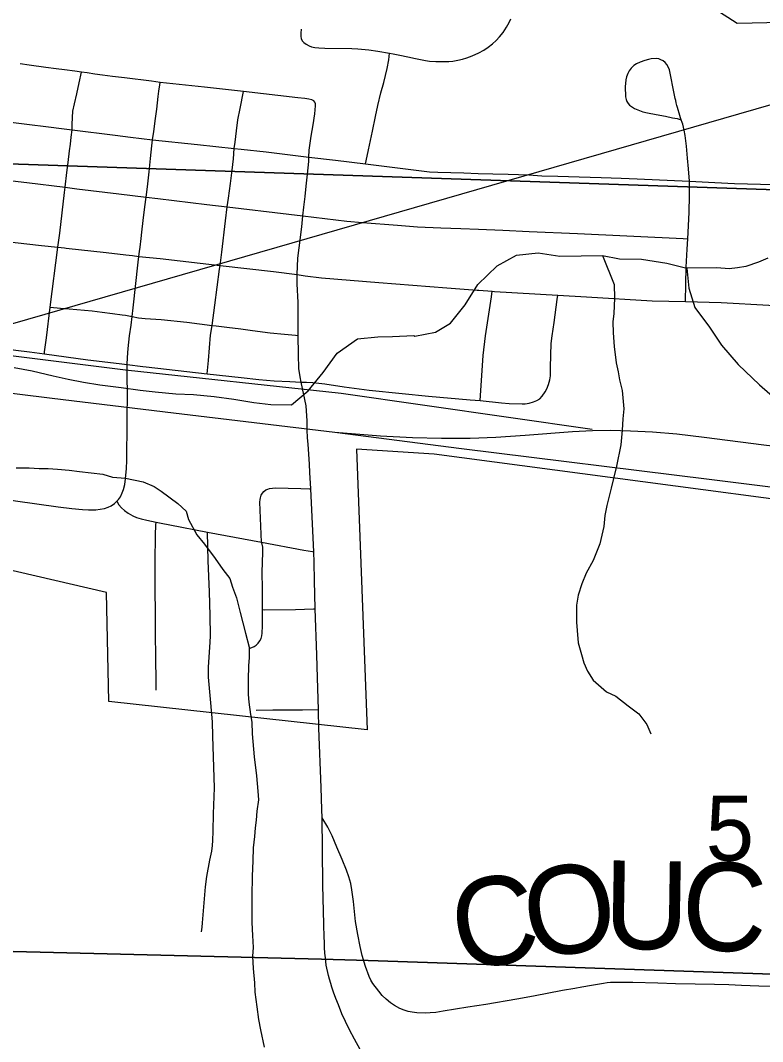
# Model space of a CAD drawing. Extents: x 0 to 34, y 0 to 22.
# Drawn here: x 14.532 to 15.01, y 17.412 to 18.07 of the extents above; entities that cross this region are included whole.
import ezdxf

# ---------------------------------------------------------------- set-up
doc = ezdxf.new("R2010")
doc.units = 0
for name, color, linetype in [('GM_X_City_Street', 7, 'Continuous'), ('GM_X_Corporation', 7, 'Continuous'), ('GM_X_County_Road', 7, 'Continuous'), ('GM_X_Major_River', 7, 'Continuous'), ('GM_X_Minor_River', 7, 'Continuous'), ('GM_X_Rail_Line', 7, 'Continuous'), ('GM_X_Section_Text', 7, 'Continuous'), ('GM_X_State_Route', 7, 'Continuous'), ('GM_X_Township_Road', 7, 'Continuous'), ('GM_X_Township_Road_Text', 7, 'Continuous'), ('SH_Text', 7, 'Continuous')]:
    doc.layers.add(name, color=color, linetype=linetype)

msp = doc.modelspace()

# ---------------------------------------------------------------- linework, layer by layer
at = {"layer": 'GM_X_City_Street'}
for points in [[(14.76987, 18.04884), (14.77212, 18.04844), (14.7765, 18.04767), (14.78166, 18.04664), (14.78647, 18.04554), (14.79308, 18.04416), (14.79561, 18.04378), (14.79962, 18.04349), (14.8081, 18.0436), (14.81055, 18.04383), (14.81391, 18.04436), (14.81687, 18.04502), (14.81962, 18.04585), (14.82308, 18.04715), (14.82737, 18.04911), (14.8305, 18.05081), (14.83345, 18.0527), (14.83621, 18.05484), (14.8385, 18.05698), (14.84067, 18.05935), (14.84299, 18.06226), (14.84527, 18.06561), (14.84695, 18.06868), (14.84809, 18.07102)], [(14.71298, 18.06429), (14.71278, 18.06188), (14.71265, 18.05969), (14.71288, 18.05834), (14.71355, 18.0569), (14.71459, 18.05575), (14.71604, 18.05474), (14.71801, 18.05367), (14.71956, 18.0531), (14.72173, 18.05262), (14.72427, 18.05237), (14.72815, 18.05223), (14.74546, 18.05199), (14.74935, 18.05176), (14.75646, 18.05117), (14.76227, 18.05029), (14.76987, 18.04884)], [(14.75439, 17.97764), (14.75473, 17.97967), (14.75618, 17.98662), (14.75886, 17.99873), (14.76078, 18.00809), (14.76222, 18.01513), (14.76417, 18.02343), (14.76609, 18.02999), (14.76837, 18.03909), (14.76929, 18.04464), (14.76987, 18.04884)], [(14.7179, 17.98196), (14.71815, 17.98637), (14.71926, 17.99549), (14.72064, 18.0028), (14.72181, 18.00988), (14.72221, 18.01499), (14.72211, 18.01628), (14.72166, 18.01742), (14.72096, 18.01815), (14.71973, 18.01876), (14.7179, 18.0192), (14.71531, 18.01968), (14.7107, 18.02014), (14.67577, 18.02432), (14.65062, 18.02693), (14.622, 18.03011), (14.61638, 18.0308), (14.59906, 18.03298), (14.59144, 18.03397), (14.58489, 18.03483), (14.57992, 18.0355), (14.57503, 18.03615), (14.57129, 18.03666), (14.56705, 18.03724), (14.56049, 18.03814), (14.55506, 18.03888), (14.54839, 18.03978), (14.53767, 18.04122), (14.53193, 18.04197)], [(14.963, 17.96648), (14.96256, 17.97437), (14.96189, 17.98122), (14.9612, 17.98892), (14.96037, 17.99599), (14.95973, 17.99934), (14.95874, 18.0031), (14.95834, 18.00436), (14.95777, 18.00609), (14.95736, 18.00731), (14.95691, 18.00873), (14.95643, 18.01027), (14.95581, 18.01234), (14.95534, 18.01398), (14.95501, 18.01518), (14.95455, 18.01697), (14.95421, 18.01835), (14.95389, 18.01972), (14.95315, 18.02297), (14.95252, 18.02617), (14.95112, 18.03382), (14.95022, 18.03826), (14.94945, 18.04017), (14.94851, 18.04166), (14.94748, 18.04286), (14.94615, 18.04398), (14.94469, 18.04473), (14.94331, 18.04525), (14.9417, 18.04541), (14.9385, 18.0453), (14.93659, 18.04493), (14.93424, 18.04421), (14.93126, 18.04311), (14.92889, 18.04198), (14.92731, 18.04102), (14.92548, 18.03928), (14.92425, 18.03745), (14.92337, 18.03579), (14.92259, 18.03358), (14.9221, 18.03165), (14.92178, 18.02949), (14.92171, 18.0274), (14.92189, 18.0209), (14.92223, 18.019), (14.92277, 18.01782), (14.92353, 18.01656), (14.92453, 18.01533), (14.92578, 18.01447), (14.92772, 18.01338), (14.92986, 18.01236), (14.93308, 18.01115), (14.93603, 18.01041), (14.94164, 18.00944), (14.9476, 18.00827), (14.95212, 18.00737), (14.95362, 18.00706), (14.95506, 18.00675), (14.95641, 18.00646), (14.95777, 18.00609)], [(14.54744, 17.85518), (14.54762, 17.85658), (14.54875, 17.86551), (14.55127, 17.88542), (14.55616, 17.92395), (14.55732, 17.93307), (14.56042, 17.95925), (14.5608, 17.96254), (14.56193, 17.97212), (14.5627, 17.9784), (14.56367, 17.98601), (14.56422, 17.99038), (14.56476, 17.99478), (14.56533, 17.99959), (14.56542, 18.00323), (14.56582, 18.01156), (14.56687, 18.01631), (14.56836, 18.02267), (14.5699, 18.02973), (14.57129, 18.03666)], [(14.61712, 17.99317), (14.6179, 17.99849), (14.61901, 18.00692), (14.61985, 18.01283), (14.62034, 18.01688), (14.62086, 18.02106), (14.62127, 18.02437), (14.62179, 18.02845), (14.622, 18.03011)], [(14.65233, 17.84236), (14.6531, 17.85105), (14.65456, 17.86733), (14.65552, 17.87344), (14.65733, 17.88652), (14.66019, 17.90976), (14.66063, 17.91218), (14.66184, 17.92066), (14.66423, 17.94085), (14.66532, 17.94996), (14.66608, 17.95564), (14.66734, 17.96496), (14.66851, 17.97364), (14.66931, 17.9809), (14.66983, 17.98761), (14.67034, 17.99167), (14.67127, 17.99882), (14.6722, 18.00609), (14.67351, 18.01335), (14.67577, 18.02432)], [(14.49509, 18.00812), (14.49845, 18.00791), (14.50719, 18.00686), (14.52592, 18.0045), (14.53785, 18.00305), (14.54846, 18.00175), (14.56024, 18.00028), (14.56533, 17.99959), (14.59308, 17.99608), (14.60298, 17.99483), (14.61712, 17.99317)], [(14.61498, 17.97256), (14.61589, 17.98109), (14.61671, 17.98927), (14.61712, 17.99317)], [(14.61712, 17.99317), (14.64603, 17.99012), (14.66983, 17.98761), (14.67415, 17.98715), (14.69025, 17.98534), (14.7179, 17.98196)], [(14.724, 17.62616), (14.72338, 17.64665), (14.72292, 17.66143), (14.722, 17.69098), (14.7215, 17.70927), (14.72118, 17.72093), (14.72096, 17.72776), (14.71911, 17.76842), (14.71859, 17.77879), (14.7183, 17.78432), (14.71735, 17.79708), (14.71704, 17.80125), (14.71684, 17.80643), (14.71666, 17.81216), (14.7161, 17.82178), (14.71286, 17.8371), (14.71215, 17.84055), (14.71145, 17.84593), (14.71114, 17.85477), (14.71107, 17.86707), (14.71089, 17.88843), (14.7104, 17.90045), (14.71027, 17.90631), (14.7108, 17.91691), (14.71167, 17.92361), (14.71323, 17.93706), (14.71398, 17.9441), (14.71465, 17.94981), (14.71538, 17.95659), (14.71604, 17.96321), (14.71693, 17.97104), (14.71777, 17.97905), (14.7179, 17.98196)], [(14.7179, 17.98196), (14.73502, 17.98008), (14.75439, 17.97764), (14.79564, 17.97259), (14.80102, 17.97218), (14.81761, 17.97178), (14.82694, 17.97152), (14.83644, 17.97126), (14.8462, 17.9709), (14.8596, 17.97052), (14.86798, 17.96998), (14.87834, 17.96966), (14.89212, 17.9692), (14.90612, 17.96881), (14.91912, 17.96842), (14.92947, 17.96802), (14.963, 17.96648)], [(14.51384, 17.96829), (14.53625, 17.96558), (14.5608, 17.96254), (14.56829, 17.96165), (14.59548, 17.95829), (14.61309, 17.95614), (14.62055, 17.95525), (14.65221, 17.9515), (14.66532, 17.94996), (14.70486, 17.9452), (14.71398, 17.9441), (14.74229, 17.94064), (14.75243, 17.93992), (14.77487, 17.93808), (14.78783, 17.93706), (14.80285, 17.93649), (14.81586, 17.9359), (14.82713, 17.93552), (14.84282, 17.93486), (14.85977, 17.934), (14.89086, 17.93268), (14.95911, 17.92952), (14.96205, 17.92932)], [(14.60829, 17.91806), (14.60877, 17.9211), (14.60913, 17.92408), (14.60982, 17.92964), (14.61032, 17.93365), (14.61117, 17.94114), (14.61217, 17.94992), (14.61309, 17.95614), (14.61391, 17.96273), (14.61498, 17.97256)], [(14.96045, 17.8889), (14.96072, 17.90022), (14.96105, 17.91108), (14.96168, 17.92279), (14.96205, 17.92932), (14.96288, 17.94621), (14.96305, 17.95731), (14.963, 17.96648)], [(14.963, 17.96648), (14.97939, 17.96557), (14.99211, 17.96506), (15.05047, 17.96342), (15.07989, 17.96229), (15.08594, 17.9622), (15.10877, 17.96158), (15.14487, 17.9602), (15.15632, 17.95933)], [(14.52497, 17.92744), (14.53623, 17.92618), (14.54566, 17.92513), (14.55616, 17.92395), (14.56046, 17.92347), (14.56146, 17.92336)], [(14.56146, 17.92336), (14.58732, 17.92045), (14.59996, 17.91901), (14.60424, 17.91852), (14.60829, 17.91806)], [(14.82833, 17.82514), (14.82862, 17.83157), (14.83008, 17.85412), (14.8316, 17.86687), (14.83547, 17.89208), (14.83603, 17.89558)], [(14.61097, 17.84714), (14.613, 17.8469), (14.65233, 17.84236), (14.67426, 17.84003), (14.68565, 17.83886), (14.69546, 17.83792), (14.70558, 17.83739), (14.71286, 17.8371), (14.71643, 17.83701), (14.72051, 17.83673), (14.72808, 17.83592), (14.74054, 17.83406), (14.7568, 17.83192), (14.77802, 17.82969), (14.79485, 17.82797), (14.82185, 17.82569), (14.82833, 17.82514), (14.84201, 17.82371), (14.84685, 17.82337), (14.85529, 17.82303), (14.85723, 17.82315), (14.85978, 17.82356), (14.86269, 17.82432), (14.86475, 17.82521), (14.86657, 17.82635), (14.86823, 17.82806), (14.87007, 17.83072), (14.87118, 17.83278), (14.87234, 17.83549), (14.87313, 17.83853), (14.87346, 17.84114), (14.87362, 17.8468), (14.87407, 17.86185), (14.87469, 17.86692), (14.87601, 17.87537), (14.8779, 17.89023), (14.87823, 17.893)], [(14.55127, 17.88542), (14.55785, 17.88477), (14.56334, 17.88424), (14.57327, 17.88347), (14.57815, 17.88289), (14.58479, 17.88205), (14.59129, 17.8813), (14.59752, 17.88049), (14.59981, 17.88013), (14.60189, 17.87969), (14.60399, 17.87928), (14.60803, 17.87851), (14.61236, 17.87813), (14.62262, 17.8774), (14.63921, 17.87566), (14.65552, 17.87344), (14.65813, 17.87325), (14.66501, 17.87253), (14.67404, 17.87135), (14.68145, 17.8703), (14.69301, 17.86882), (14.70221, 17.86786), (14.7092, 17.86723), (14.71107, 17.86707)], [(14.49053, 17.86534), (14.49131, 17.86444), (14.49232, 17.86372), (14.49347, 17.86314), (14.49484, 17.86262), (14.49647, 17.86218), (14.49858, 17.86179), (14.5045, 17.86098), (14.51118, 17.86005), (14.51621, 17.85937), (14.52316, 17.85842), (14.52906, 17.85767), (14.53782, 17.85648), (14.54744, 17.85518), (14.57539, 17.85138), (14.59556, 17.84896), (14.60077, 17.84835), (14.61097, 17.84714)], [(14.67944, 17.66549), (14.68122, 17.66618), (14.6826, 17.66683), (14.68393, 17.66769), (14.68525, 17.66896), (14.68632, 17.67041), (14.68713, 17.67187), (14.68761, 17.67375), (14.68785, 17.67549), (14.68792, 17.6802), (14.68807, 17.69063), (14.68792, 17.70409), (14.68771, 17.71455), (14.68824, 17.72754), (14.68812, 17.73087), (14.68769, 17.73273), (14.68725, 17.73404), (14.68636, 17.75972), (14.68646, 17.76145), (14.68668, 17.76265), (14.68722, 17.76421), (14.68792, 17.7655), (14.68886, 17.76667), (14.69009, 17.7676), (14.6914, 17.76818), (14.69241, 17.76846), (14.69645, 17.76893), (14.71276, 17.7686), (14.71832, 17.76844), (14.71911, 17.76842)], [(14.59413, 17.7604), (14.59552, 17.75813), (14.59709, 17.7562), (14.599, 17.75437), (14.6015, 17.75259), (14.60442, 17.75093), (14.60685, 17.7498), (14.60974, 17.74892), (14.61341, 17.74807), (14.61951, 17.74683), (14.62267, 17.74625), (14.62833, 17.74516), (14.65252, 17.74054), (14.68725, 17.73404), (14.71457, 17.72891), (14.7201, 17.72792), (14.72096, 17.72776)], [(14.61957, 17.63863), (14.61942, 17.64816), (14.61931, 17.65573), (14.61921, 17.66419), (14.61914, 17.6707), (14.61882, 17.72108), (14.61906, 17.7388), (14.61931, 17.74494), (14.61951, 17.74683)], [(14.68807, 17.69063), (14.68946, 17.69052), (14.7093, 17.69067), (14.72074, 17.69098), (14.722, 17.69098)], [(14.68391, 17.62584), (14.69464, 17.62608), (14.70342, 17.62597), (14.71366, 17.62604), (14.724, 17.62616)]]:
    msp.add_lwpolyline(points, dxfattribs=at)
at = {"layer": 'GM_X_Corporation'}
for points in [[(13.27416, 17.49656), (14.09544, 17.48114), (14.72599, 17.4654), (14.75606, 17.4645), (15.84263, 17.42782), (15.88436, 17.42688), (16.48069, 17.41608), (16.48857, 17.73917), (16.51683, 18.87067), (16.5174, 18.89349), (16.54748, 18.89293), (16.75204, 18.88908), (16.75322, 19.06144), (16.75475, 19.28374), (16.76523, 20.32799), (16.7661, 20.4), (11.50006, 20.4)], [(16.44192, 14.8642), (16.44975, 15.46263), (16.45161, 15.59641), (16.46108, 16.1288), (16.46029, 16.26174), (16.46891, 16.92454), (16.47027, 17.00356), (16.4704, 17.01044), (16.48069, 17.41608), (15.88436, 17.42688), (15.84263, 17.42782), (14.75606, 17.4645), (14.72599, 17.4654), (14.09544, 17.48114), (13.27416, 17.49656)]]:
    msp.add_lwpolyline(points, dxfattribs=at)
for points in [[(14.51245, 18.92359), (15.51969, 18.90882), (15.50037, 17.94467), (14.4926, 17.9788)], [(14.12416, 17.75411), (14.12384, 17.99777), (14.12545, 18.21705), (14.2457, 18.21434), (14.49034, 18.19103), (14.78118, 18.15667), (14.88115, 18.1407), (14.99378, 18.06821), (15.18555, 18.07245), (15.22414, 18.0733), (15.17106, 17.87356), (15.20251, 17.8656), (15.18408, 17.73958), (14.79859, 17.79075), (14.74846, 17.79396), (14.75535, 17.61323), (14.58889, 17.63142), (14.58748, 17.70162), (14.28481, 17.77174), (14.28379, 17.80545), (14.2579, 17.80636), (14.24004, 17.80235), (14.21513, 17.79424), (14.20893, 17.79132)], [(14.4926, 17.9788), (15.50037, 17.94467), (15.48158, 16.92817), (14.47088, 16.98467)]]:
    msp.add_lwpolyline(points, close=True, dxfattribs=at)
at = {"layer": 'GM_X_County_Road'}
for points in [[(14.72434, 17.61429), (14.72424, 17.61828), (14.72416, 17.62132), (14.724, 17.62616)], [(14.72786, 17.47663), (14.72775, 17.47945), (14.72747, 17.48801), (14.72681, 17.51299), (14.72662, 17.53602), (14.72634, 17.55647), (14.72616, 17.56191), (14.72583, 17.57596), (14.72434, 17.61429)], [(14.73041, 17.45499), (14.72908, 17.46164), (14.7285, 17.4662), (14.72823, 17.46933), (14.72802, 17.47288), (14.72786, 17.47663)], [(14.75086, 17.40723), (14.7472, 17.41386), (14.74406, 17.41995), (14.74149, 17.4252), (14.73917, 17.43028), (14.73686, 17.43602), (14.73525, 17.44006), (14.73367, 17.44426), (14.73264, 17.44731), (14.73195, 17.4498), (14.73118, 17.45263), (14.73041, 17.45499)]]:
    msp.add_lwpolyline(points, dxfattribs=at)
at = {"layer": 'GM_X_Major_River'}
for points in [[(14.78547, 17.86706), (14.78617, 17.86676), (14.79942, 17.86922), (14.80922, 17.87505), (14.81855, 17.88694), (14.82673, 17.89996), (14.8391, 17.91189), (14.85154, 17.91889), (14.86557, 17.92023), (14.87964, 17.91814), (14.90698, 17.91852), (14.91801, 17.9164), (14.93207, 17.91621), (14.94842, 17.91378)], [(14.94842, 17.91378), (14.96137, 17.91055), (14.96268, 17.89766), (14.96664, 17.88519), (14.97592, 17.87242), (14.98367, 17.86077), (14.99446, 17.84839), (15.00831, 17.8353), (15.01983, 17.82522)], [(14.52809, 17.84646), (14.53949, 17.84437), (14.55319, 17.84119), (14.5627, 17.83907), (14.57259, 17.83696), (14.58323, 17.83524), (14.5969, 17.83357), (14.60906, 17.83187), (14.61893, 17.8309), (14.63222, 17.8296), (14.6436, 17.82903), (14.65689, 17.82774), (14.66942, 17.82605), (14.68235, 17.82399), (14.69336, 17.82265), (14.70663, 17.82249), (14.71747, 17.8314), (14.72712, 17.84332), (14.73601, 17.85561), (14.74912, 17.86493), (14.76237, 17.86629), (14.77184, 17.86645), (14.78547, 17.86706)]]:
    msp.add_lwpolyline(points, dxfattribs=at)
at = {"layer": 'GM_X_Minor_River'}
for points in [[(14.90698, 17.91852), (14.91462, 17.89991), (14.91484, 17.89118), (14.91434, 17.88129), (14.91372, 17.87596), (14.9139, 17.86874), (14.9145, 17.86002), (14.91592, 17.84942), (14.9172, 17.84375), (14.91809, 17.83846), (14.91978, 17.83166), (14.92085, 17.81991), (14.92025, 17.81343), (14.91968, 17.8062), (14.91878, 17.79668), (14.9161, 17.78294), (14.91267, 17.76879), (14.90992, 17.75771), (14.90857, 17.75121), (14.908, 17.74398), (14.90525, 17.7329), (14.90097, 17.72215), (14.89662, 17.71407), (14.89377, 17.70715), (14.8913, 17.69988), (14.89032, 17.69339), (14.89023, 17.68237), (14.89074, 17.67707), (14.89133, 17.6691), (14.89342, 17.66156), (14.89507, 17.65628), (14.89748, 17.65102), (14.90105, 17.64503), (14.90959, 17.63765), (14.91573, 17.63476), (14.92348, 17.6285), (14.93044, 17.62335), (14.93554, 17.61664), (14.93821, 17.61061)], [(15.01359, 17.91683), (15.00758, 17.9144), (14.99931, 17.91153), (14.99402, 17.91064), (14.98872, 17.91013), (14.98074, 17.91069), (14.96137, 17.91055)], [(14.52935, 17.78182), (14.5377, 17.78183), (14.54415, 17.78146), (14.54985, 17.78148), (14.55592, 17.78111), (14.56352, 17.78036), (14.56998, 17.77961), (14.58517, 17.77774), (14.59125, 17.77586), (14.59961, 17.77511), (14.611, 17.77286), (14.61823, 17.76983), (14.62279, 17.7668), (14.63345, 17.75885), (14.63878, 17.75392), (14.64032, 17.74861), (14.64567, 17.73874), (14.65063, 17.73268), (14.6575, 17.72358), (14.66246, 17.71637), (14.66703, 17.71069), (14.66857, 17.70499), (14.67125, 17.69816), (14.67356, 17.68867), (14.67703, 17.67539), (14.67934, 17.66628), (14.67936, 17.65945), (14.679, 17.65451), (14.67865, 17.6454), (14.67868, 17.6359), (14.67908, 17.63097), (14.68025, 17.623), (14.68102, 17.61806), (14.68143, 17.61047), (14.68262, 17.59566), (14.68418, 17.58351), (14.68497, 17.57364), (14.68537, 17.56795), (14.68426, 17.56073), (14.6839, 17.55503), (14.68316, 17.55009), (14.6828, 17.5444), (14.68206, 17.53718), (14.68171, 17.52883), (14.68137, 17.51896), (14.68103, 17.50604), (14.68109, 17.48896), (14.6815, 17.4806), (14.68191, 17.47301), (14.68155, 17.46731), (14.68196, 17.45934), (14.68275, 17.45023), (14.68315, 17.44415), (14.68432, 17.43466), (14.68549, 17.42669), (14.68665, 17.41986), (14.68897, 17.40885)]]:
    msp.add_lwpolyline(points, dxfattribs=at)
at = {"layer": 'GM_X_Rail_Line'}
for points in [[(14.90033, 17.80647), (14.73866, 17.82966), (14.59978, 17.84477), (14.43811, 17.86491), (14.35463, 17.87631), (14.29632, 17.88267), (14.25073, 17.88558), (14.23059, 17.88691), (13.97059, 17.88399), (13.8235, 17.8824), (13.80468, 17.88346), (13.7901, 17.88532), (13.76545, 17.88797)], [(13.74001, 17.86404), (13.79479, 17.85776), (13.8449, 17.85469), (13.92574, 17.85403), (14.08342, 17.85653), (14.25612, 17.85826), (14.28777, 17.85708), (14.31905, 17.85522), (14.36121, 17.85072), (14.46202, 17.838), (14.55254, 17.82673), (14.63073, 17.81732), (14.73449, 17.80474)], [(14.73449, 17.80474), (14.76404, 17.80248), (14.78458, 17.80142), (14.8034, 17.80102), (14.82168, 17.80102), (14.83838, 17.80155), (14.8572, 17.80301), (14.88768, 17.80527), (14.90053, 17.80593), (14.91219, 17.80606), (14.92505, 17.8058), (14.93936, 17.80513), (14.95486, 17.80381), (14.97262, 17.80155), (15.01105, 17.79678), (15.10766, 17.78512), (15.25939, 17.7667), (15.27622, 17.76472), (15.29106, 17.76246), (15.30802, 17.75981), (15.32353, 17.75703)], [(14.73449, 17.80474), (14.81612, 17.79427), (14.97567, 17.77465), (15.12502, 17.75597), (15.14542, 17.75345), (15.16225, 17.7512), (15.18001, 17.74855), (15.19896, 17.74537), (15.21804, 17.74166), (15.23527, 17.73808), (15.25144, 17.7345), (15.26893, 17.73026), (15.29066, 17.72469), (15.31226, 17.71833)]]:
    msp.add_lwpolyline(points, dxfattribs=at)
at = {"layer": 'GM_X_State_Route'}
for points in [[(14.60399, 17.87928), (14.60457, 17.885), (14.60788, 17.91438), (14.60829, 17.91806)], [(14.60829, 17.91806), (14.622, 17.9167), (14.66063, 17.91218)], [(14.66063, 17.91218), (14.69506, 17.90824), (14.71027, 17.90631)], [(14.71027, 17.90631), (14.71549, 17.90549), (14.7261, 17.90422), (14.76304, 17.90124), (14.80669, 17.89785), (14.82632, 17.89632)], [(14.82632, 17.89632), (14.82736, 17.89624), (14.83603, 17.89558)], [(14.83603, 17.89558), (14.83737, 17.89549), (14.87823, 17.893)], [(14.87823, 17.893), (14.89683, 17.89204), (14.93913, 17.8895), (14.96045, 17.8889)], [(14.96045, 17.8889), (14.98342, 17.88842), (15.0143, 17.88665), (15.02884, 17.88565), (15.07549, 17.88285), (15.07745, 17.88277)], [(14.60077, 17.84835), (14.60096, 17.85297), (14.60134, 17.85866), (14.60229, 17.86687), (14.60329, 17.87375), (14.60399, 17.87928)], [(14.60089, 17.82108), (14.6009, 17.82202), (14.60077, 17.84835)], [(14.59413, 17.7604), (14.5952, 17.76157), (14.59645, 17.76329), (14.59764, 17.76566), (14.59842, 17.76787), (14.59921, 17.7711), (14.59978, 17.77482), (14.60032, 17.78147), (14.60065, 17.78657), (14.60083, 17.81159), (14.60089, 17.82108)], [(14.37722, 17.7951), (14.38189, 17.79392), (14.40236, 17.78861), (14.42323, 17.78346), (14.43503, 17.78049), (14.44945, 17.77703), (14.46381, 17.77344), (14.49075, 17.76717), (14.50163, 17.76494), (14.51659, 17.76251), (14.52875, 17.76062), (14.5563, 17.75685), (14.56513, 17.75565), (14.57193, 17.755), (14.57587, 17.75485), (14.58064, 17.75492), (14.58344, 17.7552), (14.58629, 17.75577), (14.5885, 17.75651), (14.59043, 17.75748), (14.59256, 17.75898), (14.59413, 17.7604)]]:
    msp.add_lwpolyline(points, dxfattribs=at)
at = {"layer": 'GM_X_Township_Road'}
for points in [[(14.65573, 17.61838), (14.6547, 17.63055), (14.65328, 17.6471), (14.65321, 17.65346), (14.65418, 17.66963), (14.65446, 17.67358), (14.65418, 17.68682), (14.6538, 17.70202), (14.65294, 17.72192), (14.65269, 17.73127), (14.65252, 17.74054)], [(14.64866, 17.48302), (14.64905, 17.48602), (14.64937, 17.48883), (14.65122, 17.51192), (14.65212, 17.51858), (14.65415, 17.52912), (14.65528, 17.53508), (14.65569, 17.53861), (14.65593, 17.5419), (14.65612, 17.54791), (14.65649, 17.5591), (14.65715, 17.57581), (14.65607, 17.60896), (14.65573, 17.61838)], [(14.75665, 17.45425), (14.75428, 17.46068), (14.75225, 17.46772), (14.75086, 17.47367), (14.74938, 17.48123), (14.74798, 17.48967), (14.74659, 17.50266), (14.74562, 17.51018), (14.74493, 17.51411), (14.74367, 17.51852), (14.74217, 17.52285), (14.7393, 17.52956), (14.73595, 17.53752), (14.7328, 17.54484), (14.73005, 17.55035), (14.72634, 17.55647)], [(14.91218, 17.45032), (14.90998, 17.45012), (14.90779, 17.44979), (14.90392, 17.44912), (14.89986, 17.44841), (14.89381, 17.4474), (14.88923, 17.44664), (14.88128, 17.44521), (14.86249, 17.44153), (14.85178, 17.4396), (14.83181, 17.43623), (14.82032, 17.43446), (14.80434, 17.43188), (14.79964, 17.43107), (14.79595, 17.43077), (14.79288, 17.43067), (14.78732, 17.43088), (14.78451, 17.43126), (14.78184, 17.43184), (14.77925, 17.43263), (14.77642, 17.43377), (14.77298, 17.43558), (14.77045, 17.43726), (14.76761, 17.4396), (14.76508, 17.44214), (14.76284, 17.44474), (14.75914, 17.44975), (14.75783, 17.45192), (14.75665, 17.45425)], [(15.08444, 17.44527), (15.08159, 17.4455), (15.07773, 17.4458), (15.07407, 17.44595), (15.06952, 17.44608), (15.05938, 17.44637), (15.05302, 17.44658), (15.04361, 17.44688), (15.02899, 17.44737), (15.01837, 17.44775), (15.00767, 17.44815), (14.99667, 17.44857), (14.98842, 17.44887), (14.97925, 17.44913), (14.96673, 17.44939), (14.95398, 17.44966), (14.94268, 17.44995), (14.92661, 17.45038), (14.91218, 17.45032)]]:
    msp.add_lwpolyline(points, dxfattribs=at)
at = {"layer": 'SH_Text'}
msp.add_line((15.49839, 18.1549), (13.96758, 17.71321), dxfattribs=at)

# ---------------------------------------------------------------- texts
at = {"layer": 'GM_X_Section_Text'}
msp.add_text('5', height=0.04186, rotation=0.00001, dxfattribs=at).set_placement((14.97356, 17.52888))
at = {"layer": 'GM_X_Township_Road_Text'}
for s, rotation, p in [('O', 8.45259, (14.86058, 17.46514)), ('U', 359.08929, (14.90759, 17.47233)), ('C', 358.38003, (14.9574, 17.47154)), ('C', 9.54381, (14.81484, 17.45745))]:
    msp.add_text(s, height=0.05682, rotation=rotation, dxfattribs=at).set_placement(p)

doc.saveas('drawing.dxf')
